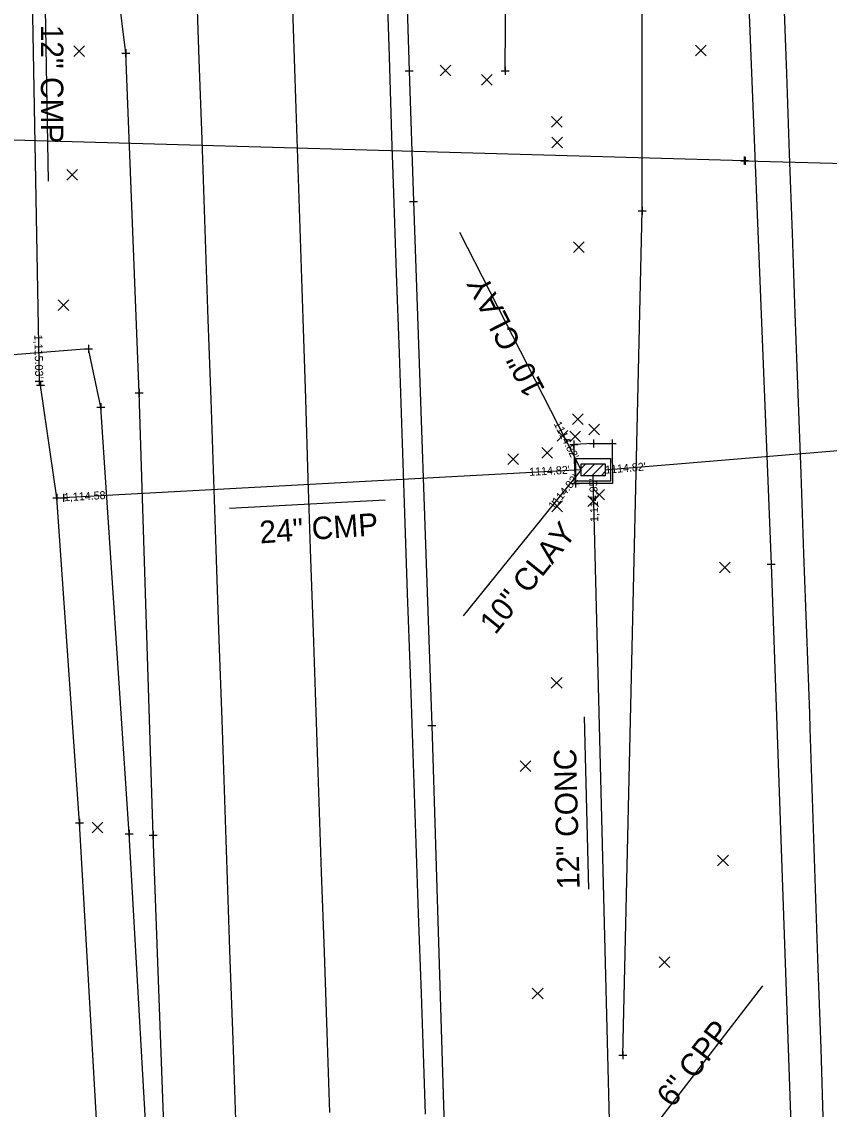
# Model space of a CAD drawing. Extents: x 146022 to 147632, y 437624 to 440659.
# Drawn here: x 146918.2 to 147019.1, y 438466 to 438601.8 of the extents above; entities that cross this region are included whole.
import ezdxf

# ---------------------------------------------------------------- set-up
doc = ezdxf.new("R2010")
doc.units = 0
for name, color, linetype in [('_CIVIL_CONSTRUCTION', 7, 'Continuous'), ('DR_Channel', 7, 'Continuous'), ('DR_P_Ditch', 7, 'Continuous'), ('DR_P_Paved_Gutter', 7, 'Continuous'), ('DR_X_Storm_Sewer', 7, 'Continuous'), ('DR_X_Text', 7, 'Continuous'), ('DT_X_Triangles', 7, 'Continuous'), ('GE_P_Alignment_100_Distances', 7, 'Continuous'), ('PF_X_Ground_Line', 7, 'Continuous'), ('PV_P_Curb', 7, 'Continuous'), ('RD_P_Anchor_Assembly', 7, 'Continuous'), ('RD_P_Fence', 7, 'Continuous'), ('RD_P_GR_Lt_Replaced', 7, 'Continuous'), ('SC_Scratch1', 7, 'Continuous'), ('SC_Scratch3', 7, 'Continuous'), ('UT_X_Electric', 7, 'Continuous'), ('UT_X_Overhead_Electric', 7, 'Continuous')]:
    doc.layers.add(name, color=color, linetype=linetype)

msp = doc.modelspace()

# ---------------------------------------------------------------- linework, layer by layer
at = {"layer": '_CIVIL_CONSTRUCTION'}
for p, q in [((146924.75, 438597.46), (146926.08, 438598.8)), ((146924.75, 438598.8), (146926.08, 438597.46)), ((147002.38, 438597.56), (147003.72, 438598.9)), ((147002.38, 438598.9), (147003.72, 438597.56)), ((146970.5, 438595.07), (146971.83, 438596.41)), ((146970.5, 438596.41), (146971.83, 438595.07)), ((146975.66, 438593.89), (146976.99, 438595.22)), ((146975.66, 438595.22), (146976.99, 438593.89)), ((146984.38, 438588.66), (146985.71, 438589.99)), ((146984.38, 438589.99), (146985.71, 438588.66)), ((146984.43, 438586.06), (146985.76, 438587.39)), ((146984.43, 438587.39), (146985.76, 438586.06)), ((146923.86, 438582.02), (146925.19, 438583.36)), ((146923.86, 438583.36), (146925.19, 438582.02)), ((146987.15, 438573), (146988.48, 438574.34)), ((146987.15, 438574.34), (146988.48, 438573)), ((146922.77, 438565.74), (146924.1, 438567.08)), ((146922.77, 438567.08), (146924.1, 438565.74)), ((146987.02, 438551.53), (146988.35, 438552.86)), ((146987.02, 438552.86), (146988.35, 438551.53)), ((146985.1, 438549.45), (146986.43, 438550.78)), ((146985.1, 438550.78), (146986.43, 438549.45)), ((146986.67, 438549.34), (146988, 438550.68)), ((146986.67, 438550.68), (146988, 438549.34)), ((146989.05, 438550.23), (146990.38, 438551.57)), ((146989.05, 438551.57), (146990.38, 438550.23)), ((146978.93, 438546.51), (146980.26, 438547.85)), ((146978.93, 438547.85), (146980.26, 438546.51)), ((146983.19, 438547.32), (146984.52, 438548.65)), ((146983.19, 438548.65), (146984.52, 438547.32)), ((146988.93, 438541.28), (146990.27, 438542.61)), ((146988.93, 438542.61), (146990.27, 438541.28)), ((146989.69, 438542.09), (146991.02, 438543.42)), ((146989.69, 438543.42), (146991.02, 438542.09)), ((146984.43, 438540.63), (146985.76, 438541.97)), ((146984.43, 438541.97), (146985.76, 438540.63)), ((147005.38, 438532.98), (147006.72, 438534.31)), ((147005.38, 438534.31), (147006.72, 438532.98)), ((146984.37, 438518.58), (146985.71, 438519.91)), ((146984.37, 438519.91), (146985.71, 438518.58)), ((146980.49, 438508.19), (146981.83, 438509.52)), ((146980.49, 438509.52), (146981.83, 438508.19)), ((146927.02, 438500.5), (146928.35, 438501.84)), ((146927.02, 438501.84), (146928.35, 438500.5)), ((147005.15, 438496.38), (147006.49, 438497.71)), ((147005.15, 438497.71), (147006.49, 438496.38)), ((146997.85, 438483.69), (146999.19, 438485.03)), ((146997.85, 438485.03), (146999.19, 438483.69)), ((146982, 438479.78), (146983.34, 438481.12)), ((146982, 438481.12), (146983.34, 438479.78))]:
    msp.add_line(p, q, dxfattribs=at)
at = {"layer": 'DR_Channel'}
msp.add_lwpolyline([(146993.31, 438472.76), (146995.72, 438578.19), (146995.68, 438627.98), (146995.78, 438662.55)], dxfattribs=at)
at = {"layer": 'DR_P_Ditch'}
msp.add_line((146989.64, 438549.13), (146987.17, 438549.02), dxfattribs=at)
msp.add_lwpolyline([(146989.64, 438549.13), (146991.96, 438549.14), (146992.03, 438544.15), (146987.41, 438544.15), (146987.17, 438549.02)], dxfattribs=at)
at = {"layer": 'DR_P_Paved_Gutter'}
msp.add_lwpolyline([(146978.6, 438595.67), (146978.94, 438641.64), (146979.94, 438703.5), (146984.39, 438761.32), (146986.69, 438784.31)], dxfattribs=at)
at = {"layer": 'DR_X_Storm_Sewer'}
for p, q in [((146918.33, 438670), (146920.42, 438556.95)), ((146988.1, 438545.87), (146972.96, 438575.51)), ((146991.1, 438545.87), (147064.28, 438551.9)), ((146988.1, 438545.87), (146923.46, 438542.34)), ((146988.1, 438545.87), (146973.37, 438527.61)), ((146991.79, 438459.44), (146989.6, 438545.12)), ((146993.29, 438458.69), (147010.8, 438481.43))]:
    msp.add_line(p, q, dxfattribs=at)
at = {"layer": 'DR_X_Text'}
for p, q in [((146921.58, 438581.91), (146921.18, 438603.43)), ((146944.19, 438541.07), (146963.63, 438542.13)), ((146988.47, 438514.99), (146989.02, 438493.47))]:
    msp.add_line(p, q, dxfattribs=at)
at = {"layer": 'DT_X_Triangles'}
for p, q in [((146989.6, 438547.29), (146989.6, 438547.29)), ((146989.6, 438546.62), (146989.6, 438546.62)), ((146989.6, 438546.62), (146989.6, 438546.62)), ((146989.6, 438546.62), (146989.6, 438546.62)), ((146988.1, 438545.87), (146988.1, 438545.87)), ((146989.6, 438545.87), (146989.6, 438545.87)), ((146989.6, 438545.12), (146989.6, 438545.12)), ((146991.1, 438545.87), (146991.1, 438545.87)), ((146989.6, 438544.45), (146989.6, 438544.45))]:
    msp.add_line(p, q, dxfattribs=at)
at = {"layer": 'GE_P_Alignment_100_Distances'}
msp.add_lwpolyline([(146878.79, 438588.15), (147008.47, 438584.5), (147008.59, 438584.46), (147110.26, 438581.75)], dxfattribs=at)
at = {"layer": 'PF_X_Ground_Line'}
msp.add_lwpolyline([(146944.2, 438145.61), (146942.51, 438206.23), (146939.98, 438265.94), (146939.05, 438324.76), (146936.01, 438383.62), (146934.98, 438441.73), (146931.66, 438500.39), (146928.09, 438553.7), (146926.58, 438560.96), (146916.64, 438560.16)], dxfattribs=at)
at = {"layer": 'PV_P_Curb'}
msp.add_lwpolyline([(146952.01, 438604.72), (146952.33, 438594.72), (146952.66, 438584.73), (146952.99, 438574.73), (146953.32, 438564.74), (146953.65, 438554.74), (146953.98, 438544.75), (146954.31, 438534.75), (146954.61, 438525.57), (146954.95, 438515.58), (146955.3, 438505.58), (146955.64, 438495.59), (146955.99, 438485.6), (146956.33, 438475.6), (146956.68, 438465.61)], dxfattribs=at)
at = {"layer": 'RD_P_Anchor_Assembly'}
for p, q in [((146930.74, 438597.9), (146931.74, 438597.9)), ((146931.24, 438598.4), (146931.24, 438597.4)), ((146931.24, 438597.9), (146931.24, 438597.9)), ((146966.1, 438595.69), (146967.1, 438595.69)), ((146966.6, 438596.19), (146966.6, 438595.19)), ((146966.6, 438595.69), (146966.6, 438595.69)), ((146978.1, 438595.67), (146979.1, 438595.67)), ((146978.6, 438596.17), (146978.6, 438595.17)), ((146978.6, 438595.67), (146978.6, 438595.67)), ((147007.97, 438584.5), (147008.97, 438584.5)), ((147008.09, 438584.46), (147009.09, 438584.46)), ((147008.47, 438585), (147008.47, 438584)), ((147008.47, 438584.5), (147008.47, 438584.5)), ((147008.59, 438584.96), (147008.59, 438583.96)), ((147008.59, 438584.46), (147008.59, 438584.46)), ((146966.66, 438579.39), (146967.66, 438579.39)), ((146967.16, 438579.89), (146967.16, 438578.89)), ((146967.16, 438579.39), (146967.16, 438579.39)), ((146995.22, 438578.19), (146996.22, 438578.19)), ((146995.72, 438578.69), (146995.72, 438577.69)), ((146995.72, 438578.19), (146995.72, 438578.19)), ((146926.58, 438561.46), (146926.58, 438560.46)), ((146926.08, 438560.96), (146927.08, 438560.96)), ((146926.58, 438560.96), (146926.58, 438560.96)), ((146920.07, 438556.43), (146921.07, 438556.43)), ((146920.57, 438556.93), (146920.57, 438555.93)), ((146920.57, 438556.43), (146920.57, 438556.43)), ((146932.91, 438555.97), (146932.91, 438554.97)), ((146932.41, 438555.47), (146933.41, 438555.47)), ((146932.91, 438555.47), (146932.91, 438555.47)), ((146927.59, 438553.7), (146928.59, 438553.7)), ((146928.09, 438554.2), (146928.09, 438553.2)), ((146928.09, 438553.7), (146928.09, 438553.7)), ((146986.67, 438549.02), (146987.67, 438549.02)), ((146987.17, 438549.52), (146987.17, 438548.52)), ((146987.17, 438549.02), (146987.17, 438549.02)), ((146989.14, 438549.13), (146990.14, 438549.13)), ((146989.64, 438549.63), (146989.64, 438548.63)), ((146989.64, 438549.13), (146989.64, 438549.13)), ((146991.46, 438549.14), (146992.46, 438549.14)), ((146991.96, 438549.64), (146991.96, 438548.64)), ((146991.96, 438549.14), (146991.96, 438549.14)), ((146986.91, 438544.15), (146987.91, 438544.15)), ((146987.41, 438544.65), (146987.41, 438543.65)), ((146987.41, 438544.15), (146987.41, 438544.15)), ((146922.13, 438542.37), (146923.13, 438542.37)), ((146922.63, 438542.87), (146922.63, 438541.87)), ((146922.63, 438542.37), (146922.63, 438542.37)), ((147011.35, 438534.06), (147012.35, 438534.06)), ((147011.85, 438534.56), (147011.85, 438533.56)), ((147011.85, 438534.06), (147011.85, 438534.06)), ((146968.96, 438513.91), (146969.96, 438513.91)), ((146969.46, 438514.41), (146969.46, 438513.41)), ((146969.46, 438513.91), (146969.46, 438513.91)), ((146924.95, 438501.75), (146925.95, 438501.75)), ((146925.45, 438502.25), (146925.45, 438501.25)), ((146925.45, 438501.75), (146925.45, 438501.75)), ((146931.16, 438500.39), (146932.16, 438500.39)), ((146931.66, 438500.89), (146931.66, 438499.89)), ((146931.66, 438500.39), (146931.66, 438500.39)), ((146934.13, 438500.21), (146935.13, 438500.21)), ((146934.63, 438500.71), (146934.63, 438499.71)), ((146934.63, 438500.21), (146934.63, 438500.21)), ((146993.31, 438473.26), (146993.31, 438472.26)), ((146992.81, 438472.76), (146993.81, 438472.76)), ((146993.31, 438472.76), (146993.31, 438472.76))]:
    msp.add_line(p, q, dxfattribs=at)
at = {"layer": 'RD_P_Fence'}
msp.add_lwpolyline([(146936.46, 438144.06), (146934.88, 438206.37), (146934.35, 438264.58), (146933.16, 438323.89), (146930.71, 438381.13), (146928.93, 438440.82), (146925.45, 438501.75), (146922.63, 438542.37), (146920.57, 438556.43)], dxfattribs=at)
at = {"layer": 'RD_P_GR_Lt_Replaced'}
for p, q in [((146966.6, 438595.69), (146967.16, 438579.39)), ((147011.85, 438534.06), (147014.55, 438456.21))]:
    msp.add_line(p, q, dxfattribs=at)
for points in [[(146949.53, 439101.12), (146951.47, 439043.06), (146953.42, 438986.87), (146955.3, 438928.33), (146957.21, 438869.74), (146959.24, 438814.61), (146960.64, 438770.62), (146962.64, 438718.51), (146964.89, 438649.27), (146966.6, 438595.69)], [(147007.62, 438631.92), (147008.71, 438612.13), (147011.85, 438534.06)], [(146946.9, 438144.61), (146944.75, 438205.42), (146943.15, 438266.6), (146940.8, 438324.49), (146938.64, 438383.77), (146936.82, 438441.33), (146934.63, 438500.21), (146932.91, 438555.47), (146931.24, 438597.9), (146929.33, 438613.44)], [(146967.16, 438579.39), (146969.46, 438513.91), (146971.29, 438454.33), (146973.72, 438390.43), (146975.93, 438328.61), (146978.09, 438271.89), (146980.36, 438202.45), (146982.75, 438144.54)]]:
    msp.add_lwpolyline(points, dxfattribs=at)
at = {"layer": 'SC_Scratch3'}
for points in [[(147018.39, 438463.59), (147018.06, 438473.58), (147017.72, 438483.58), (147017.39, 438493.57), (147017.05, 438503.56), (147016.71, 438513.56), (147016.65, 438515.42), (147016.29, 438525.42), (147015.93, 438535.41), (147015.57, 438545.4), (147015.21, 438555.4), (147014.85, 438565.39), (147014.49, 438575.38), (147014.13, 438585.38), (147013.77, 438595.37), (147013.41, 438605.36), (147013.26, 438609.73)], [(146963.78, 438607.49), (146964.1, 438597.5), (146964.43, 438587.51), (146964.66, 438580.4), (146965.01, 438570.41), (146965.35, 438560.42), (146965.69, 438550.42), (146966.04, 438540.43), (146966.38, 438530.43), (146966.73, 438520.44), (146967.07, 438510.44), (146967.41, 438500.45), (146967.76, 438490.46), (146968.1, 438480.46), (146968.44, 438470.47), (146968.62, 438465.4)], [(146944.96, 438464.68), (146944.62, 438474.67), (146944.27, 438484.67), (146943.93, 438494.66), (146943.59, 438504.65), (146943.24, 438514.65), (146942.9, 438524.64), (146942.56, 438534.64), (146942.22, 438544.63), (146941.87, 438554.63), (146941.53, 438564.62), (146941.19, 438574.61), (146941.1, 438577.12), (146940.75, 438587.11), (146940.4, 438597.1), (146940.05, 438607.1)]]:
    msp.add_lwpolyline(points, dxfattribs=at)
at = {"layer": 'UT_X_Electric'}
for p, q in [((146988.1, 438546.62), (146988.61, 438546.62)), ((146988.1, 438546.06), (146988.1, 438546.62)), ((146988.1, 438546.04), (146988.68, 438546.62)), ((146988.32, 438545.12), (146989.82, 438546.62)), ((146988.99, 438546.62), (146989.41, 438546.62)), ((146989.45, 438545.12), (146990.95, 438546.62)), ((146989.82, 438546.62), (146990.21, 438546.62)), ((146990.59, 438546.62), (146991.1, 438546.62)), ((146991.1, 438546.62), (146991.1, 438546.06)), ((146988.1, 438545.12), (146988.1, 438545.68)), ((146988.61, 438545.12), (146988.1, 438545.12)), ((146989.41, 438545.12), (146988.99, 438545.12)), ((146990.21, 438545.12), (146989.79, 438545.12)), ((146990.58, 438545.12), (146991.1, 438545.64)), ((146991.1, 438545.12), (146990.59, 438545.12)), ((146991.1, 438545.68), (146991.1, 438545.12))]:
    msp.add_line(p, q, dxfattribs=at)
for points in [[(146987.43, 438547.29), (146991.76, 438547.29), (146991.76, 438544.45), (146987.43, 438544.45)], [(146988.1, 438546.62), (146991.1, 438546.62), (146991.1, 438545.12), (146988.1, 438545.12)], [(146988.1, 438546.62), (146991.1, 438546.62), (146991.1, 438545.12), (146988.1, 438545.12)]]:
    msp.add_lwpolyline(points, close=True, dxfattribs=at)
at = {"layer": 'UT_X_Overhead_Electric'}
for p, q in [((146920.42, 438557.45), (146920.42, 438556.45)), ((146919.92, 438556.95), (146920.92, 438556.95)), ((146920.42, 438556.95), (146920.42, 438556.95)), ((146922.96, 438542.34), (146923.96, 438542.34)), ((146923.46, 438542.84), (146923.46, 438541.84)), ((146923.46, 438542.34), (146923.46, 438542.34))]:
    msp.add_line(p, q, dxfattribs=at)

# ---------------------------------------------------------------- texts
at = {"layer": 'DR_X_Text'}
for s, rotation, p in [('12" CMP', 270, (146920.62, 438601.46)), ('10" CLAY', 117.0562, (146983.64, 438555.88)), ('24" CMP', 4, (146948.02, 438536.66)), ('10" CLAY', 51.0989, (146977.37, 438525.16)), ('12" CONC', 91.4646, (146987.92, 438493.51)), ('6" CPP', 52.4049, (146999.53, 438466.08))]:
    msp.add_text(s, height=2.8, rotation=rotation, dxfattribs=at).set_placement(p)
at = {"layer": 'SC_Scratch1'}
for s, rotation, p in [("1,115.03'", 271.0581, (146919.81, 438562.72)), ("1114.82'", 297.0562, (146984.65, 438551.61)), ("1114.82'", 3.1289, (146981.63, 438545.1)), ("1114.82'", 4.708, (146991.14, 438545.37)), ("1114.82'", 51.0989, (146984.7, 438540.83)), ("1,114.95'", 91.4646, (146990.25, 438539.35)), ("1,114.58'", 3.1289, (146923.52, 438541.93))]:
    msp.add_text(s, height=1, rotation=rotation, dxfattribs=at).set_placement(p)

doc.saveas('drawing.dxf')
